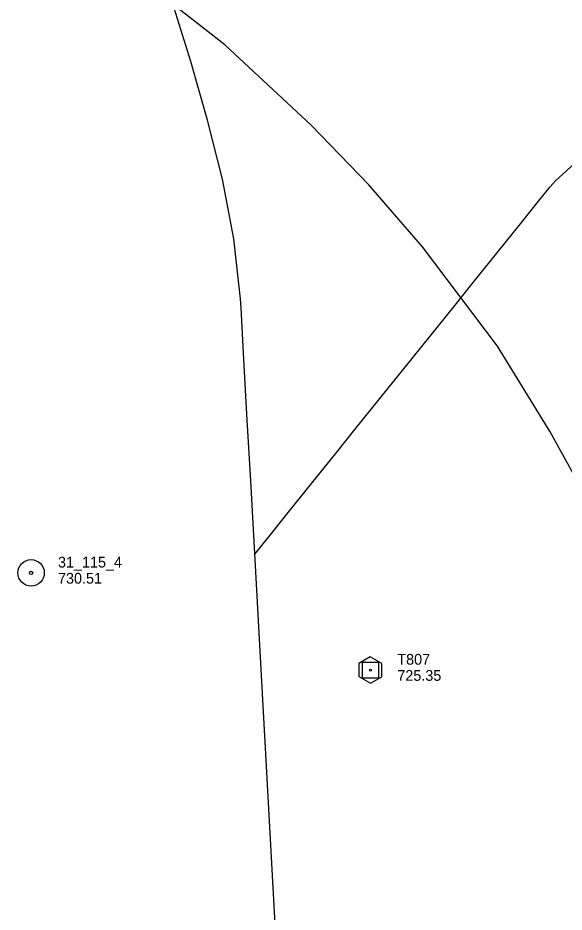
# Model space of a CAD drawing. Extents: x 589250 to 1188077, y 162953 to 363065.
# Drawn here: x 593581 to 593885.9, y 163454 to 163952.9 of the extents above; entities that cross this region are included whole.
import ezdxf

# ---------------------------------------------------------------- set-up
doc = ezdxf.new("R2010")
doc.units = 0
for name, color, linetype in [('E_DRN_DrainTile', 7, 'Continuous'), ('E_MAP_Control', 7, 'Continuous'), ('E_MAP_Limits', 7, 'Continuous'), ('E_MAP_PassPoints', 7, 'Continuous')]:
    doc.layers.add(name, color=color, linetype=linetype)

msp = doc.modelspace()

# ---------------------------------------------------------------- linework, layer by layer
at = {"layer": 'E_DRN_DrainTile'}
for points in [[(593735.28, 163254.42), (593733.41, 163288.28), (593731.54, 163322.14), (593729.67, 163355.99), (593727.8, 163389.85), (593725.92, 163423.71), (593724.05, 163457.57), (593722.18, 163491.42), (593720.31, 163525.28), (593718.44, 163559.14), (593716.57, 163592.99), (593714.7, 163626.85), (593712.83, 163660.71), (593710.96, 163694.56), (593709.08, 163728.42), (593707.21, 163762.28), (593705.62, 163791.16), (593705.31, 163796.13), (593701.49, 163829.68), (593695.16, 163862.86), (593686.94, 163895.78), (593677.48, 163928.56), (593667.4, 163961.32)], [(593713.21, 163653.72), (593722.53, 163665.3), (593731.85, 163676.89), (593741.17, 163688.47), (593750.49, 163700.05), (593759.81, 163711.63), (593769.13, 163723.21), (593778.45, 163734.79), (593787.77, 163746.37), (593797.09, 163757.96), (593806.41, 163769.54), (593815.73, 163781.12), (593825.05, 163792.7), (593834.37, 163804.28), (593843.68, 163815.86), (593853, 163827.44), (593862.32, 163839.03), (593871.64, 163850.61), (593878.14, 163858.68), (593881.04, 163862.07), (593891.68, 163871.65)]]:
    msp.add_lwpolyline(points, dxfattribs=at)
at = {"layer": 'E_MAP_Control'}
for p, q in [((593773.29, 163584.54), (593773.29, 163593.54)), ((593773.29, 163593.54), (593782.29, 163593.54)), ((593773.29, 163584.54), (593773.29, 163593.54)), ((593773.29, 163593.54), (593782.29, 163593.54)), ((593773.29, 163584.54), (593773.29, 163593.54)), ((593773.29, 163593.54), (593782.29, 163593.54)), ((593782.29, 163593.54), (593782.29, 163584.54)), ((593782.29, 163593.54), (593782.29, 163584.54)), ((593782.29, 163593.54), (593782.29, 163584.54)), ((593782.29, 163584.54), (593773.29, 163584.54)), ((593782.29, 163584.54), (593773.29, 163584.54)), ((593782.29, 163584.54), (593773.29, 163584.54))]:
    msp.add_line(p, q, dxfattribs=at)
msp.add_lwpolyline([(593771.37, 163592.81), (593771.37, 163585.42), (593777.83, 163581.69), (593784.23, 163585.35), (593784.23, 163592.68), (593777.71, 163596.41)], close=True, dxfattribs=at)
msp.add_lwpolyline([(593771.37, 163592.81), (593771.37, 163585.42), (593777.83, 163581.69), (593784.23, 163585.35), (593784.23, 163592.68), (593777.71, 163596.41)], close=True, dxfattribs=at)
msp.add_lwpolyline([(593771.37, 163592.81), (593771.37, 163585.42), (593777.83, 163581.69), (593784.23, 163585.35), (593784.23, 163592.68), (593777.71, 163596.41)], close=True, dxfattribs=at)
msp.add_circle((593777.79, 163589.04), 0.546, dxfattribs=at)
msp.add_circle((593777.79, 163589.04), 0.546, dxfattribs=at)
msp.add_circle((593777.79, 163589.04), 0.546, dxfattribs=at)
at = {"layer": 'E_MAP_Limits'}
for p, q in [((593696.52, 163937.85), (593633.07, 163987.66)), ((593744.78, 163893.05), (593696.52, 163937.85)), ((593776.83, 163859.71), (593744.78, 163893.05)), ((593806.82, 163825.15), (593776.83, 163859.71)), ((593848.61, 163769.85), (593806.82, 163825.15)), ((593878.06, 163721.94), (593848.61, 163769.85)), ((593895.86, 163689.63), (593878.06, 163721.94))]:
    msp.add_line(p, q, dxfattribs=at)
at = {"layer": 'E_MAP_PassPoints'}
for radius in [7.38, 7.38, 7.38, 0.945, 0.945, 0.945]:
    msp.add_circle((593588.43, 163643.28), radius, dxfattribs=at)

# ---------------------------------------------------------------- texts
at = {"layer": 'E_MAP_Control'}
for s, p in [('T807', (593792.79, 163592.05)), ('T807', (593792.79, 163592.05)), ('T807', (593792.79, 163592.05)), ('725.35', (593792.79, 163583.05)), ('725.35', (593792.79, 163583.05)), ('725.35', (593792.79, 163583.05))]:
    msp.add_text(s, height=6, dxfattribs=at).set_placement(p)
at = {"layer": 'E_MAP_PassPoints'}
for s, p in [('31_115_4', (593603.43, 163646.27)), ('31_115_4', (593603.43, 163646.27)), ('31_115_4', (593603.43, 163646.27)), ('730.51', (593603.43, 163637.27)), ('730.51', (593603.43, 163637.27)), ('730.51', (593603.43, 163637.27))]:
    msp.add_text(s, height=6, dxfattribs=at).set_placement(p)

doc.saveas('drawing.dxf')
